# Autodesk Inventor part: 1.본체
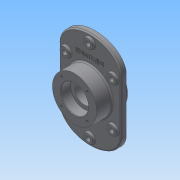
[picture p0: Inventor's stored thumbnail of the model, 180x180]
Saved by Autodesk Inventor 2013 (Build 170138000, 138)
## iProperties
Created: 2015-02
Part Number: 1.본체
Material: 일반
Document SubType Name: Modeling
Designer: Administrator
Density: 1 g/cm^3
Author: Administrator
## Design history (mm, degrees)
sketch "스케치1"
  geometry: L1 (-70, 60)-(-70, -60); L2 (70, 60)-(70, -60); L3 (-70, 0)-(70, 0); L4 (0, 110)-(0, 0); L5 (-70, 60)-(70, 60); 3 further points; 2 other entities
  constraints: 10 end point, 4 midpoint, 3 horizontal, 3 parallel, 1 coincident, 1 perpendicular, 1 symmetric about line, 1 vertical, 9 other
  dimensions: "d4" = 140 distance between parallel lines of L2 L1; "d5" = 60 distance of L2.start L3.end; "d58" = 50 vertical distance of L2.start L4.start
extrude "돌출1" new body sketch "스케치1" distance "d6" = 12; taper "d7" = 0 deg
sketch "스케치2"
  geometry: C1 r 50 at (0, 0); 1 further point
  constraints: 1 centre point, 1 coincident
  dimensions: "d8" = 100 diameter of C1
extrude "돌출2" join sketch "스케치2" distance "d10" = 35; taper "d11" = 0 deg
sketch "스케치3"
  geometry: C1 r 50 at (0, 0); 1 further point
  constraints: 1 centre point, 1 coincident
  dimensions: "d12" = 100 diameter of C1
extrude "돌출3" join sketch "스케치3" distance "d14" = 23; taper "d15" = 0 deg
sketch "스케치4"
  geometry: C1 r 50 at (0, 0) reference; C2 r 31 at (0, 0)
  constraints: 1 centre point, 1 coincident
  dimensions: "d16" = 62 diameter of C2
extrude "돌출4" cut sketch "스케치4" distance "d18" = 22; taper "d19" = 0 deg
sketch "스케치5"
  geometry: C1 r 50 at (0, 0) reference; C2 r 31 at (0, 0)
  constraints: 1 centre point, 1 coincident
  dimensions: "d20" = 62 diameter of C2
extrude "돌출5" cut sketch "스케치5" distance "d22" = 22; taper "d23" = 0 deg
sketch "스케치6"
  geometry: C1 r 31 at (0, 0) reference; C2 r 22.5 at (0, 0)
  constraints: 1 centre point, 1 coincident
  dimensions: "d24" = 45 diameter of C2
extrude "돌출6" cut sketch "스케치6" stored distance "d26" = 22; taper "d27" = 0 deg
sketch "스케치8"
  geometry: L1 (0, 50)-(0, 0); L2 (0, 0)-(-28.991, 28.991); C1 r 31 at (0, 0) reference; 4 further points
  constraints: 4 end point, 1 coincident, 1 vertical, 1 vertical alignment, 6 other
  dimensions: "d30" = 45 deg angle of L2 L1; "d31" = 41 distance of L1.end L2.end; "d34" = 360 deg dimension on C1.centre point (-28.991, 28.991) (derived)
hole "구멍1" sketch "스케치8" at (-28.991, 28.991), (-28.991, -28.991), (28.991, -28.991), (28.991, 28.991) diameter "d36" = 5.459; stored, may be unused: countersink angle "d40" = 90 deg, drill point angle "d42" = 120 deg; dims "d37" = 10, "d38" = 4, "d39" = 2, "d41" = 13
sketch "스케치9"
  geometry: L1 (0, 50)-(0, 0); L2 (0, 0)-(-28.991, 28.991); C1 r 31 at (0, 0) reference; 4 further points
  constraints: 4 end point, 1 coincident, 1 vertical, 1 vertical alignment, 6 other
  dimensions: "d43" = 45 deg angle of L2 L1; "d44" = 41 distance of L1.end L2.end; "d47" = 360 deg dimension on C1.centre point (-28.991, 28.991) (derived)
hole "구멍2" sketch "스케치9" at (-28.991, 28.991), (-28.991, -28.991), (28.991, -28.991), (28.991, 28.991) diameter "d49" = 5.459; stored, may be unused: countersink angle "d53" = 90 deg, drill point angle "d55" = 120 deg; dims "d50" = 10, "d51" = 4, "d52" = 2, "d54" = 13
sketch "스케치10"
  geometry: L1 (70, -60)-(70, 60) reference; L2 (-70, 60)-(-70, -60) reference; L3 (53, 60)-(53, -60); L4 (-53, -60)-(-53, 60); C1 r 50 at (0, 0) reference; C2 r 5.5 at (0, 93); C3 r 5.5 at (53, 50); C4 r 5.5 at (53, -50); C5 r 5.5 at (0, -93); C6 r 5.5 at (-53, -50); C7 r 5.5 at (-53, 50); 4 further points; 2 other entities
  constraints: 6 centre point, 5 equal radius, 4 end point, 4 point on line, 3 parallel, 10 other
  dimensions: "d71" = 11 diameter of C2; "d73" = 17 distance between parallel lines of L1 L3
extrude "돌출7" cut sketch "스케치10" stored distance "d74" = 10; taper "d75" = 0 deg
sketch "스케치12"
  geometry: L1 (70, -60)-(70, 60) reference; L2 (-70, 60)-(-70, -60) reference; C1 r 5.5 at (-53, -50) reference; C2 r 5.5 at (53, -50) reference; C3 r 5.5 at (0, 93) reference; C4 r 5.5 at (53, 50) reference; C5 r 5.5 at (0, -93) reference; C6 r 5.5 at (-53, 50) reference; C7 r 50 at (0, 0) reference; C8 r 10 at (-53, 50); C9 r 10 at (0, 93); C10 r 10 at (53, 50); C11 r 10 at (53, -50); C12 r 10 at (0, -93); C13 r 10 at (-53, -50); 3 further points; 2 other entities
  constraints: 6 centre point, 6 coincident, 5 equal radius, 2 other
  dimensions: "d76" = 20 diameter of C9
extrude "돌출8" join sketch "스케치12" distance "d78" = 5; taper "d79" = 0 deg
fillet "모깎기3" dims "d80" = 3
fillet "모깎기1" dims "d56" = 0.3
fillet "모깎기2" dims "d57" = 3
sketch "스케치11"
  geometry: C1 r 53 at (0, 0) reference; 1 further point
  constraints: 1 vertical alignment, 1 other
  dimensions: "d62" = 65 distance of C1.centre point (0, 65)
feature "엠보싱1" sketch "스케치11" dims "d63" = 1, "d64" = 0
chamfer "모따기1" distance "d65" = 1; stored, may be unused: second distance "d66" = 2, angle "d67" = 45 deg
chamfer "모따기2" distance "d68" = 1; stored, may be unused: second distance "d69" = 2, angle "d70" = 45 deg
node "솔리드1"
node "투영된 루프1"
node "투영된 루프2"
